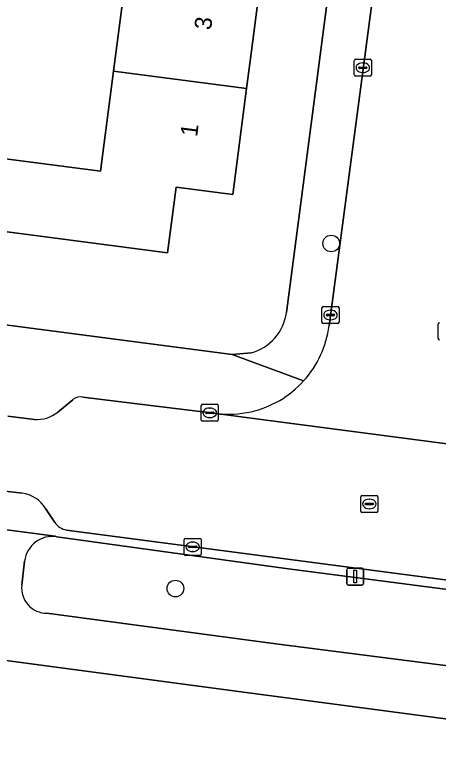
# Model space of a CAD drawing. Extents: x 162184 to 163154, y 385507 to 386516.
# Drawn here: x 162486.09 to 162511, y 386103.48 to 386146.91 of the extents above; entities that cross this region are included whole.
import ezdxf

# ---------------------------------------------------------------- set-up
doc = ezdxf.new("R2010")
doc.units = 0
for name, color, linetype in [('IMGEO_Boom', 7, 'Continuous'), ('IMGEO_Erf', 7, 'Continuous'), ('IMGEO_Groenvoorziening', 7, 'Continuous'), ('IMGEO_Kolk', 7, 'Continuous'), ('IMGEO_Lichtmast', 7, 'Continuous'), ('IMGEO_Pand', 7, 'Continuous'), ('IMGEO_Pand_nummerreeks', 7, 'Continuous'), ('IMGEO_Rijbaan_lokaal_gesloten', 7, 'Continuous'), ('IMGEO_Rijbaan_lokaal_open', 7, 'Continuous'), ('IMGEO_Rioolput', 7, 'Continuous'), ('IMGEO_Voetpad_open', 7, 'Continuous')]:
    doc.layers.add(name, color=color, linetype=linetype)

msp = doc.modelspace()

# ---------------------------------------------------------------- linework, layer by layer
at = {"layer": 'IMGEO_Boom'}
for centre in [(162504.708, 386133.457), (162495.543, 386113.165)]:
    msp.add_circle(centre, 0.489, dxfattribs=at)
at = {"layer": 'IMGEO_Erf'}
for points in [[(162505.229, 386175.825), (162500, 386176.51), (162485.436, 386178.419), (162484.936, 386174.584), (162500, 386172.62), (162500.545, 386172.549), (162500.042, 386168.686), (162503.084, 386168.289), (162502.215, 386161.625), (162501.38, 386155.217), (162500.556, 386148.897), (162500, 386144.635), (162499.732, 386142.582), (162498.919, 386136.344), (162495.581, 386136.779), (162495.077, 386132.917), (162479.792, 386134.91), (162479.088, 386129.516), (162498.874, 386126.939), (162500, 386127.02)], [(162502.068, 386129.398), (162507.733, 386172.564)], [(162485.447, 386075.601), (162491.44, 386074.827), (162491.627, 386076.276), (162494.943, 386075.848), (162494.748, 386074.337), (162500, 386073.659), (162500.637, 386073.577), (162500.838, 386075.131), (162504.152, 386074.703), (162503.946, 386073.109), (162506.753, 386072.747), (162506.966, 386074.394), (162505.677, 386074.561), (162509.27, 386098.998), (162526.485, 386096.47), (162527.457, 386103.379), (162500, 386107.017), (162478.348, 386109.886)]]:
    msp.add_lwpolyline(points, dxfattribs=at)
msp.add_lwpolyline([(162493.549, 386156.233), (162494.385, 386162.641), (162495.198, 386168.876), (162487.787, 386169.843), (162486.979, 386163.648), (162483.568, 386164.093), (162483.201, 386161.508), (162485.865, 386161.16), (162485.384, 386157.476), (162482.817, 386157.811), (162482.483, 386155.188), (162485.041, 386154.854), (162484.592, 386151.41), (162484.142, 386147.966), (162481.558, 386148.303), (162481.172, 386145.494), (162484.549, 386145.054), (162483.717, 386138.673), (162491.133, 386137.706), (162491.901, 386143.597), (162492.725, 386149.913)], close=True, dxfattribs=at)
msp.add_arc((162499.238, 386129.771), 2.855, 285.4896, 352.4875, dxfattribs=at)
at = {"layer": 'IMGEO_Groenvoorziening'}
for points in [[(162550.987, 386107.982), (162502.033, 386114.344), (162488.565, 386116.214)], [(162486.676, 386114.782), (162486.508, 386113.369)], [(162487.988, 386111.712), (162501.452, 386109.912), (162525.845, 386106.796), (162550.53, 386103.579)]]:
    msp.add_lwpolyline(points, dxfattribs=at)
for centre, radius, start, end in [((162488.319, 386114.576), 1.656, 81.4755, 172.8541), ((162487.991, 386113.204), 1.492, 173.6391, 269.9021)]:
    msp.add_arc(centre, radius, start, end, dxfattribs=at)
at = {"layer": 'IMGEO_Kolk'}
for p, q in [((162506.067, 386143.369), (162506.067, 386144.221)), ((162506.142, 386144.295), (162506.994, 386144.295)), ((162507.068, 386144.221), (162507.068, 386143.369)), ((162506.326, 386143.789), (162506.326, 386143.801)), ((162506.764, 386143.752), (162506.366, 386143.752)), ((162506.369, 386143.838), (162506.767, 386143.838)), ((162506.555, 386144.075), (162506.58, 386144.075)), ((162506.81, 386143.801), (162506.81, 386143.789)), ((162506.994, 386143.295), (162506.142, 386143.295)), ((162506.578, 386143.515), (162506.553, 386143.515)), ((162504.165, 386128.824), (162504.165, 386129.676)), ((162504.24, 386129.75), (162505.092, 386129.75)), ((162504.653, 386129.53), (162504.678, 386129.53)), ((162505.166, 386129.676), (162505.166, 386128.824)), ((162504.424, 386129.244), (162504.424, 386129.256)), ((162504.862, 386129.207), (162504.464, 386129.207)), ((162504.467, 386129.293), (162504.865, 386129.293)), ((162504.676, 386128.97), (162504.651, 386128.97)), ((162504.908, 386129.256), (162504.908, 386129.244)), ((162505.092, 386128.75), (162504.24, 386128.75)), ((162511.002, 386127.865), (162511.002, 386128.717)), ((162497.065, 386123.075), (162497.065, 386123.927)), ((162497.14, 386124.001), (162497.992, 386124.001)), ((162497.553, 386123.781), (162497.578, 386123.781)), ((162498.066, 386123.927), (162498.066, 386123.075)), ((162497.324, 386123.495), (162497.324, 386123.507)), ((162497.762, 386123.458), (162497.364, 386123.458)), ((162497.367, 386123.544), (162497.765, 386123.544)), ((162497.808, 386123.507), (162497.808, 386123.495)), ((162497.992, 386123.001), (162497.14, 386123.001)), ((162497.576, 386123.221), (162497.551, 386123.221)), ((162496.057, 386115.191), (162496.057, 386116.043)), ((162496.132, 386116.117), (162496.984, 386116.117)), ((162497.058, 386116.043), (162497.058, 386115.191)), ((162496.316, 386115.611), (162496.316, 386115.623)), ((162496.754, 386115.574), (162496.356, 386115.574)), ((162496.359, 386115.66), (162496.757, 386115.66)), ((162496.545, 386115.897), (162496.57, 386115.897)), ((162496.8, 386115.623), (162496.8, 386115.611)), ((162496.984, 386115.117), (162496.132, 386115.117)), ((162496.568, 386115.337), (162496.543, 386115.337))]:
    msp.add_line(p, q, dxfattribs=at)
for points in [[(162506.067, 386143.369), (162506.067, 386144.221)], [(162506.142, 386144.295), (162506.994, 386144.295)], [(162507.068, 386144.221), (162507.068, 386143.369)], [(162506.994, 386143.295), (162506.142, 386143.295)], [(162504.165, 386128.824), (162504.165, 386129.676)], [(162504.24, 386129.75), (162505.092, 386129.75)], [(162505.166, 386129.676), (162505.166, 386128.824)], [(162505.092, 386128.75), (162504.24, 386128.75)], [(162511.002, 386127.865), (162511.002, 386128.717)], [(162497.065, 386123.075), (162497.065, 386123.927)], [(162497.14, 386124.001), (162497.992, 386124.001)], [(162498.066, 386123.927), (162498.066, 386123.075)], [(162497.992, 386123.001), (162497.14, 386123.001)], [(162496.057, 386115.191), (162496.057, 386116.043)], [(162496.132, 386116.117), (162496.984, 386116.117)], [(162497.058, 386116.043), (162497.058, 386115.191)], [(162496.984, 386115.117), (162496.132, 386115.117)]]:
    msp.add_lwpolyline(points, dxfattribs=at)
for centre, radius, start, end in [((162506.144, 386144.219), 0.0765, 91.552, 178.448), ((162506.144, 386144.219), 0.0765, 91.552, 178.448), ((162506.992, 386144.219), 0.0765, 1.552, 88.448), ((162506.992, 386144.219), 0.0765, 1.552, 88.448), ((162506.366, 386143.798), 0.0403, 85.8775, 175.7526), ((162506.363, 386143.788), 0.0366, 178.938, 274.7102), ((162506.767, 386143.795), 0.043, 264.8664, 352.4533), ((162506.771, 386143.8), 0.0386, 1.7309, 96.639), ((162506.144, 386143.371), 0.0765, 181.552, 268.448), ((162506.144, 386143.371), 0.0765, 181.552, 268.448), ((162506.992, 386143.371), 0.0765, 271.552, 358.448), ((162506.992, 386143.371), 0.0765, 271.552, 358.448), ((162504.242, 386129.674), 0.0765, 91.552, 178.448), ((162504.242, 386129.674), 0.0765, 91.552, 178.448), ((162505.09, 386129.674), 0.0765, 1.552, 88.448), ((162505.09, 386129.674), 0.0765, 1.552, 88.448), ((162504.464, 386129.253), 0.0403, 85.8775, 175.7526), ((162504.461, 386129.243), 0.0366, 178.938, 274.7102), ((162504.865, 386129.25), 0.043, 264.8664, 352.4533), ((162504.869, 386129.255), 0.0386, 1.7309, 96.639), ((162504.242, 386128.826), 0.0765, 181.552, 268.448), ((162504.242, 386128.826), 0.0765, 181.552, 268.448), ((162505.09, 386128.826), 0.0765, 271.552, 358.448), ((162505.09, 386128.826), 0.0765, 271.552, 358.448), ((162511.079, 386128.715), 0.0765, 91.552, 178.448), ((162511.079, 386128.715), 0.0765, 91.552, 178.448), ((162511.079, 386127.867), 0.0765, 181.552, 268.448), ((162511.079, 386127.867), 0.0765, 181.552, 268.448), ((162497.142, 386123.925), 0.0765, 91.552, 178.448), ((162497.142, 386123.925), 0.0765, 91.552, 178.448), ((162497.99, 386123.925), 0.0765, 1.552, 88.448), ((162497.99, 386123.925), 0.0765, 1.552, 88.448), ((162497.364, 386123.504), 0.0403, 85.8775, 175.7526), ((162497.361, 386123.494), 0.0366, 178.938, 274.7102), ((162497.765, 386123.501), 0.043, 264.8664, 352.4533), ((162497.769, 386123.506), 0.0386, 1.7309, 96.639), ((162497.142, 386123.077), 0.0765, 181.552, 268.448), ((162497.142, 386123.077), 0.0765, 181.552, 268.448), ((162497.99, 386123.077), 0.0765, 271.552, 358.448), ((162497.99, 386123.077), 0.0765, 271.552, 358.448), ((162496.134, 386116.041), 0.0765, 91.552, 178.448), ((162496.134, 386116.041), 0.0765, 91.552, 178.448), ((162496.982, 386116.041), 0.0765, 1.552, 88.448), ((162496.982, 386116.041), 0.0765, 1.552, 88.448), ((162496.356, 386115.62), 0.0403, 85.8775, 175.7526), ((162496.353, 386115.61), 0.0366, 178.938, 274.7102), ((162496.757, 386115.617), 0.043, 264.8664, 352.4533), ((162496.761, 386115.622), 0.0386, 1.7309, 96.639), ((162496.134, 386115.193), 0.0765, 181.552, 268.448), ((162496.134, 386115.193), 0.0765, 181.552, 268.448), ((162496.982, 386115.193), 0.0765, 271.552, 358.448), ((162496.982, 386115.193), 0.0765, 271.552, 358.448)]:
    msp.add_arc(centre, radius, start, end, dxfattribs=at)
for centre, major_axis, ratio, start_param, end_param in [((162506.554, 386143.795), (-0.387, 0.002), 0.722429, 4.712389, 7.853982), ((162506.579, 386143.795), (-0.39, 0.002), 0.717154, 1.570796, 4.712389), ((162504.652, 386129.25), (-0.387, 0.002), 0.722429, 4.712389, 7.853982), ((162504.677, 386129.25), (-0.39, 0.002), 0.717154, 1.570796, 4.712389), ((162497.552, 386123.501), (-0.387, 0.002), 0.722429, 4.712389, 7.853982), ((162497.577, 386123.501), (-0.39, 0.002), 0.717154, 1.570796, 4.712389), ((162496.544, 386115.617), (-0.387, 0.002), 0.722429, 4.712389, 7.853982), ((162496.569, 386115.617), (-0.39, 0.002), 0.717154, 1.570796, 4.712389)]:
    msp.add_ellipse(centre, major_axis=major_axis, ratio=ratio, start_param=start_param, end_param=end_param, dxfattribs=at)
at = {"layer": 'IMGEO_Lichtmast'}
for p, q in [((162505.623, 386113.47), (162505.623, 386114.27)), ((162505.623, 386114.27), (162505.623, 386113.47)), ((162505.723, 386114.37), (162506.513, 386114.37)), ((162506.513, 386114.37), (162505.723, 386114.37)), ((162506.613, 386114.27), (162506.613, 386113.47)), ((162506.613, 386113.47), (162506.613, 386114.27)), ((162506.513, 386113.37), (162505.723, 386113.37)), ((162505.723, 386113.37), (162506.513, 386113.37))]:
    msp.add_line(p, q, dxfattribs=at)
msp.add_lwpolyline([(162506.043, 386114.245), (162506.193, 386114.245), (162506.193, 386113.495), (162506.043, 386113.495), (162506.043, 386114.245)], dxfattribs=at)
for centre, start, end in [((162505.723, 386114.27), 90, 180), ((162505.723, 386114.27), 90, 180), ((162506.513, 386114.27), 0, 90), ((162506.513, 386114.27), 360, 90), ((162505.723, 386113.47), 180, 270), ((162505.723, 386113.47), 180, 270), ((162506.513, 386113.47), 270, 0), ((162506.513, 386113.47), 270, 0)]:
    msp.add_arc(centre, 0.1, start, end, dxfattribs=at)
at = {"layer": 'IMGEO_Pand'}
for points in [[(162492.725, 386149.913), (162491.901, 386143.597), (162499.732, 386142.582), (162500, 386144.635), (162500.556, 386148.897), (162500, 386148.969)], [(162491.901, 386143.597), (162491.133, 386137.706), (162483.717, 386138.673), (162484.549, 386145.054), (162481.172, 386145.494), (162480.439, 386139.869), (162479.792, 386134.91), (162495.077, 386132.917), (162495.581, 386136.779), (162498.919, 386136.344), (162499.732, 386142.582)]]:
    msp.add_lwpolyline(points, close=True, dxfattribs=at)
at = {"layer": 'IMGEO_Rijbaan_lokaal_gesloten'}
for points in [[(162489.507, 386124.273), (162488.627, 386123.543)], [(162517.064, 386120.959), (162500, 386123.183), (162497.938, 386123.452), (162490.105, 386124.427)], [(162487.245, 386123.108), (162485.689, 386123.304)], [(162489.134, 386116.601), (162551.008, 386108.477), (162551.341, 386108.428), (162551.871, 386108.31), (162552.388, 386108.146), (162552.889, 386107.935), (162553.369, 386107.681), (162553.824, 386107.386), (162554.251, 386107.05), (162554.646, 386106.678), (162555.006, 386106.272), (162555.329, 386105.836), (162555.611, 386105.372), (162555.851, 386104.885), (162556.047, 386104.378), (162556.196, 386103.857), (162556.298, 386103.323), (162556.352, 386102.783), (162556.358, 386102.24), (162556.315, 386101.699), (162556.224, 386101.164), (162561.946, 386119.898), (162562.109, 386120.842)], [(162485.026, 386118.96), (162486.538, 386118.78)], [(162487.9, 386117.88), (162488.448, 386117.046)]]:
    msp.add_lwpolyline(points, dxfattribs=at)
for centre, radius, start, end in [((162489.954, 386123.775), 0.67, 76.9834, 131.8992), ((162487.385, 386125.077), 1.974, 265.9404, 309.0036), ((162486.247, 386116.859), 1.943, 31.7086, 81.3785), ((162489.403, 386117.767), 1.197, 217.0589, 256.9991)]:
    msp.add_arc(centre, radius, start, end, dxfattribs=at)
at = {"layer": 'IMGEO_Rijbaan_lokaal_open'}
for points in [[(162512.043, 386186.234), (162510.578, 386173.939), (162504.584, 386128.617)], [(162497.938, 386123.452), (162500, 386123.183), (162517.064, 386120.959)]]:
    msp.add_lwpolyline(points, dxfattribs=at)
for centre, radius, start, end in [((162498.646, 386129.395), 5.988, 317.8057, 352.5343), ((162498.652, 386129.393), 5.983, 283.0207, 317.7852), ((162498.632, 386129.721), 6.307, 263.6866, 282.5314)]:
    msp.add_arc(centre, radius, start, end, dxfattribs=at)
at = {"layer": 'IMGEO_Rioolput'}
for p, q in [((162506.45, 386117.714), (162506.45, 386118.566)), ((162506.525, 386118.64), (162507.377, 386118.64)), ((162507.451, 386118.566), (162507.451, 386117.714)), ((162506.709, 386118.134), (162506.709, 386118.146)), ((162507.147, 386118.097), (162506.749, 386118.097)), ((162506.752, 386118.183), (162507.15, 386118.183)), ((162506.938, 386118.42), (162506.963, 386118.42)), ((162507.193, 386118.146), (162507.193, 386118.134)), ((162506.961, 386117.86), (162506.936, 386117.86)), ((162507.377, 386117.64), (162506.525, 386117.64))]:
    msp.add_line(p, q, dxfattribs=at)
for points in [[(162506.45, 386117.714), (162506.45, 386118.566)], [(162506.525, 386118.64), (162507.377, 386118.64)], [(162507.451, 386118.566), (162507.451, 386117.714)], [(162507.377, 386117.64), (162506.525, 386117.64)]]:
    msp.add_lwpolyline(points, dxfattribs=at)
for centre, radius, start, end in [((162506.527, 386118.564), 0.0765, 91.552, 178.448), ((162506.527, 386118.564), 0.0765, 91.552, 178.448), ((162507.375, 386118.564), 0.0765, 1.552, 88.448), ((162507.375, 386118.564), 0.0765, 1.552, 88.448), ((162506.749, 386118.143), 0.0403, 85.8775, 175.7526), ((162506.746, 386118.133), 0.0366, 178.938, 274.7102), ((162507.15, 386118.14), 0.043, 264.8664, 352.4533), ((162507.154, 386118.145), 0.0386, 1.7309, 96.639), ((162506.527, 386117.716), 0.0765, 181.552, 268.448), ((162506.527, 386117.716), 0.0765, 181.552, 268.448), ((162507.375, 386117.716), 0.0765, 271.552, 358.448), ((162507.375, 386117.716), 0.0765, 271.552, 358.448)]:
    msp.add_arc(centre, radius, start, end, dxfattribs=at)
for centre, major_axis, ratio, start_param, end_param in [((162506.937, 386118.14), (-0.387, 0.002), 0.722429, 4.712389, 7.853982), ((162506.962, 386118.14), (-0.39, 0.002), 0.717154, 1.570796, 4.712389)]:
    msp.add_ellipse(centre, major_axis=major_axis, ratio=ratio, start_param=start_param, end_param=end_param, dxfattribs=at)
at = {"layer": 'IMGEO_Voetpad_open'}
for points in [[(162509.455, 386178.005), (162507.733, 386172.564), (162502.068, 386129.398)], [(162504.584, 386128.617), (162510.578, 386173.939)], [(162503.083, 386125.373), (162498.874, 386126.939), (162479.088, 386129.516), (162477.513, 386129.721), (162345.395, 386146.93), (162342.796, 386147.231), (162310.208, 386151.62), (162307.719, 386151.881), (162300.419, 386152.832), (162280.789, 386155.39), (162279.545, 386155.552), (162276.659, 386155.928), (162272.878, 386156.421), (162272.377, 386156.487), (162267.776, 386157.086), (162265.987, 386157.319), (162263.283, 386157.672), (162261.989, 386154.265)], [(162335.977, 386136.365), (162310.353, 386139.77), (162310.282, 386139.248), (162340.574, 386135.313), (162343.99, 386134.88), (162370.427, 386131.472), (162370.591, 386131.46), (162374.85, 386130.906), (162374.947, 386130.882), (162433.897, 386123.153), (162433.998, 386123.151), (162438.832, 386122.519), (162438.968, 386122.49), (162481.668, 386117.141), (162482.448, 386117.039), (162488.462, 386116.238), (162488.565, 386116.214), (162502.033, 386114.344), (162550.987, 386107.982)], [(162319.033, 386130.38), (162332.132, 386128.681), (162335.109, 386128.306), (162373.204, 386123.496), (162379.704, 386122.675), (162382.521, 386122.36), (162388.099, 386121.683), (162407.83, 386119.134), (162430.108, 386116.262), (162449.855, 386113.717), (162455.485, 386112.99), (162457.918, 386112.66), (162478.348, 386109.886), (162500, 386107.017), (162527.457, 386103.379), (162530.464, 386102.981), (162535.156, 386102.359), (162549.072, 386100.544)], [(162500, 386127.02), (162498.874, 386126.939), (162503.083, 386125.373)], [(162488.627, 386123.543), (162489.507, 386124.273)], [(162490.105, 386124.427), (162497.938, 386123.452)], [(162485.689, 386123.304), (162487.245, 386123.108)], [(162486.538, 386118.78), (162485.026, 386118.96)], [(162488.448, 386117.046), (162487.9, 386117.88)], [(162488.565, 386116.214), (162488.462, 386116.238), (162482.448, 386117.039)], [(162552.059, 386106.639), (162552.388, 386108.146), (162551.871, 386108.31), (162551.341, 386108.428), (162551.008, 386108.477), (162489.134, 386116.601)], [(162486.508, 386113.369), (162486.676, 386114.782)], [(162550.53, 386103.579), (162525.845, 386106.796), (162501.452, 386109.912), (162487.988, 386111.712)]]:
    msp.add_lwpolyline(points, dxfattribs=at)
for centre, radius, start, end in [((162499.238, 386129.771), 2.855, 285.4896, 352.4875), ((162498.646, 386129.395), 5.988, 317.8057, 352.5343), ((162498.652, 386129.393), 5.983, 283.0207, 317.7852), ((162489.954, 386123.775), 0.67, 76.9834, 131.8992), ((162487.385, 386125.077), 1.974, 265.9404, 309.0036), ((162498.632, 386129.721), 6.307, 263.6866, 282.5314), ((162486.247, 386116.859), 1.943, 31.7086, 81.3785), ((162489.403, 386117.767), 1.197, 217.0589, 256.9991), ((162488.319, 386114.576), 1.656, 81.4755, 172.8541), ((162487.991, 386113.204), 1.492, 173.6391, 269.9021)]:
    msp.add_arc(centre, radius, start, end, dxfattribs=at)

# ---------------------------------------------------------------- texts
at = {"layer": 'IMGEO_Pand_nummerreeks'}
for s, p in [('3', (162497.635, 386145.98)), ('1', (162496.816, 386139.704))]:
    msp.add_text(s, height=1, rotation=82.5717, dxfattribs=at).set_placement(p)

doc.saveas('drawing.dxf')
